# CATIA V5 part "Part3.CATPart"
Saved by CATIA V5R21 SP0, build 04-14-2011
Part number: Part3
Bounding box of the stored display mesh (mm): x 10 to 10, y -103.562 to -103.562, z 31.77 to 111.77
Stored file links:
  D:\CATIA V5R21 E-RESOURCES\CATIA-V5R21\catia-v5r21-prt\c16-catia-v5r20-prt\Sperical Joint-(Fig16-27)\CAT_V5R21_Part3.CATPart
  D:\CATIA V5R21 E-RESOURCES\CATIA-V5R21\catia-v5r21-prt\c16-catia-v5r20-prt\Sperical Joint-(Fig16-27)\Product1_mechanisam.CATProduct
  D:\CATIA V5R21 E-RESOURCES\CATIA-V5R21\catia-v5r21-prt\c16-catia-v5r20-prt\Sperical Joint-(Fig16-27)\Part1.CATPart
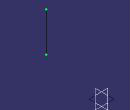
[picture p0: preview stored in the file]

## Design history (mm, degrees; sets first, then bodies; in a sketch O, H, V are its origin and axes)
Set1
  Plane1: linked copy from another document
Body1 (main body)
  Sketch1 on Plane1, origin (0, -103.5621, 0), H (-1, 0, 0), V (0, 0, 1)
    line L1 (-10, 111.7697) -> (-10, 31.7697)
    vertical: L1 V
